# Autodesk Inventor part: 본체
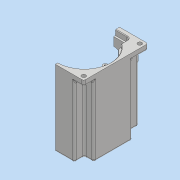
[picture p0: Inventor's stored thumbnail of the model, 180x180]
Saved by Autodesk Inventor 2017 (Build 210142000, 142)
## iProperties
Part Number: 본체
Material: 일반
Document SubType Name: Modeling
Designer: user
Density: 1 g/cm^3
Appearance: 기본값
Author: user
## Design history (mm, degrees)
sketch "스케치1"
  geometry: L1 (-49, 60)-(49, 60); L2 (49, 60)-(49, -50); L3 (49, -50)-(-49, -50); L4 (-49, -50)-(-49, 60); 2 further points
  constraints: 8 end point, 2 parallel, 1 horizontal, 1 midpoint, 1 perpendicular, 1 vertical alignment
  dimensions: "d0" = 98 distance of L2.end L3.end; "d1" = 110 distance of L1.end L2.end; "d2" = 50 distance from line of point (0, 0) L3
extrude "돌출1" new body sketch "스케치1" distance "d3" = 130; taper "d4" = 0 deg
sketch "스케치9"
  geometry: L1 (-49, 60)-(-33, 60); L2 (-33, 60)-(-33, 33); L3 (-33, 33)-(-49, 33); L4 (-49, 33)-(-49, 60); L5 (49, 60)-(33, 60); L6 (33, 60)-(33, 33); L7 (33, 33)-(49, 33); L8 (49, 33)-(49, 60); L9 (-49, -50)-(-33, -50); L10 (-33, -50)-(-33, -33); L11 (-33, -33)-(-49, -33); L12 (-49, -33)-(-49, -50); L13 (49, -50)-(33, -50); L14 (33, -50)-(33, -33); L15 (33, -33)-(49, -33); L16 (49, -33)-(49, -50); 1 further point
  constraints: 32 end point, 8 parallel, 4 horizontal, 4 perpendicular
  dimensions: "d84" = 16 distance of L2.end L3.end; "d85" = 27 distance of L1.end L2.end; "d86" = 16 distance of L7.end L6.end; "d87" = 27 distance of L6.end L5.end; "d88" = 16 distance of L11.end L10.end; "d89" = 17 distance of L10.end L9.end; "d90" = 16 distance of L14.end L15.end; "d91" = 17 distance of L13.end L14.end
extrude "돌출9" cut sketch "스케치9" distance "d92" = 120; taper "d93" = 0 deg
fillet "모깎기12" dims "d94" = 3
sketch "스케치2"
  geometry: L1 (-23, 50)-(23, 50); L2 (23, 50)-(23, 35.143); L3 (-23, 35.143)-(-23, 50); A1 r 42 centre (0, 0) between (-23, 35.143) and (23, 35.143); 2 further points
  constraints: 6 end point, 2 point on circle, 1 centre point, 1 coincident, 1 horizontal, 1 midpoint, 1 parallel, 1 perpendicular, 1 vertical alignment
  dimensions: "d5" = 84 diameter of A1; "d6" = 50 distance from line of point (0, 0) L1; "d7" = 46 distance of L1.start L1.end
extrude "돌출2" cut sketch "스케치2" distance "d8" = 121; taper "d9" = 0 deg
sketch "스케치3"
  geometry: L1 (-23, 35.143)-(-23, 50) reference; L2 (-23, 50)-(23, 50) reference; L3 (23, 50)-(23, 35.143) reference; L4 (-26, 36.729)-(-26, 53); L5 (-26, 53)-(26, 53); L6 (26, 53)-(26, 36.729); A1 r 42 centre (0, 0) between (-23, 35.143) and (23, 35.143) reference; A2 r 45 centre (0, 0) between (-26, 36.729) and (26, 36.729)
  constraints: 6 end point, 2 point on circle, 1 centre point, 3 other
  dimensions: "d10" = 3 radial gap between concentric circles of A2 A1
extrude "돌출3" cut sketch "스케치3" distance "d11" = 9; taper "d12" = 0 deg
fillet "모깎기1" dims "d13" = 6
fillet "모깎기2" dims "d14" = 3
fillet "모깎기3" dims "d15" = 3
fillet "모깎기4" dims "d16" = 6
sketch "스케치4"
  geometry: L1 (36, 4)-(41.809, 4); L2 (36, -4)-(41.809, -4); A1 r 45 centre (0, 0) between (-27.188, 35.859) and (27.188, 35.859) reference; A2 r 42 centre (0, 0) between (-25.375, 33.468) and (25.375, 33.468) reference; A3 r 4 centre (36, 0) between (36, 4) and (36, -4)
  constraints: 4 end point, 4 point on circle, 2 horizontal, 2 tangent, 1 centre point, 1 horizontal alignment
  dimensions: "d17" = 8 diameter of A3; "d18" = 36 distance of A3.centre A1.centre
extrude "돌출4" join sketch "스케치4" stored distance "d19" = 9; taper "d20" = 0 deg
hole "구멍1" diameter "d23" = 3.242; stored, may be unused: countersink angle "d27" = 90 deg, drill point angle "d29" = 118 deg; dims "d21" = 10, "d22" = 10, "d24" = 7, "d25" = 4, "d26" = 2, "d28" = 9
sketch "스케치5"
  geometry: A1 r 42 centre (0, 0) between (-41.809, -4) and (41.809, -4) reference; A2 r 42 centre (0, 0) between (41.809, 4) and (25.375, 33.468) reference; A3 r 21 centre (0, 11) between (8.978, -7.984) and (-8.978, -7.984); A4 r 15 centre (0, -20) between (-8.978, -7.984) and (8.978, -7.984)
  constraints: 4 point on circle, 2 centre point, 2 vertical alignment
  dimensions: "d30" = 42 diameter of A3; "d31" = 30 diameter of A4; "d32" = 11 distance of A1.centre A3.centre; "d33" = 20 distance of A4.centre A1.centre
extrude "돌출5" join sketch "스케치5" distance "d34" = 7; taper "d35" = 0 deg
fillet "모깎기5" dims "d36" = 3
hole "구멍2" diameter "d39" = 19; stored, may be unused: countersink angle "d43" = 90 deg, drill point angle "d45" = 0 deg; dims "d37" = 10, "d38" = 10, "d40" = 7, "d41" = 22, "d42" = 7, "d44" = 10
fillet "모깎기6" dims "d46" = 0.3
chamfer "모따기1" distance "d47" = 1; stored, may be unused: second distance "d48" = 2, angle "d49" = 45 deg
fillet "모깎기7" dims "d50" = 3
hole "구멍3" diameter "d53" = 28; stored, may be unused: countersink angle "d57" = 90 deg, drill point angle "d59" = 0 deg; dims "d51" = 10, "d52" = 10, "d54" = 7, "d55" = 35, "d56" = 10, "d58" = 10
sketch "스케치6"
  geometry: L1 (27, -16)-(-27, -16); L2 (-27, -16)-(-27, 38); L3 (-27, 38)-(27, 38); L4 (27, 38)-(27, -16); L5 (27, -16)-(-27, 38); L6 (-27, -16)-(27, 38); C1 r 14 at (0, 11) reference; 1 further point
  constraints: 12 end point, 2 midpoint, 2 parallel, 1 horizontal, 1 perpendicular
  dimensions: "d60" = 54 distance of L2.end L3.end; "d61" = 54 distance of L1.end L2.end
extrude "돌출6" join sketch "스케치6" distance "d62" = 7; taper "d63" = 0 deg
sketch "스케치7"
  geometry: C1 r 14 at (0, 11) reference; C2 r 16 at (0, 11); 1 further point
  constraints: 1 centre point, 1 coincident
  dimensions: "d64" = 32 diameter of C2
extrude "돌출7" cut sketch "스케치7" distance "d65" = 8.3; taper "d66" = 0 deg
chamfer "모따기2" distance "d67" = 0.8; stored, may be unused: second distance "d68" = 2, angle "d69" = 30 deg
fillet "모깎기8" dims "d70" = 0.3
fillet "모깎기9" dims "d71" = 0.3
fillet "모깎기10" dims "d72" = 3
fillet "모깎기11" dims "d73" = 3
fillet "모깎기13" dims "d95" = 3
fillet "모깎기14" dims "d96" = 3
fillet "모깎기15" dims "d97" = 3
sketch "스케치10"
  geometry: L1 (-46, 60)-(46, 60) reference; A1 r 45 centre (0, 0) between (-27.188, 35.859) and (27.188, 35.859) reference; 4 further points
  constraints: 2 horizontal alignment, 2 vertical alignment
  dimensions: "d98" = 84 distance of point (42, 53) point (-42, 53); "d99" = 42 horizontal distance of A1.centre point (42, 53) (= 0.5 x d98); "d100" = 96 distance of point (42, -43) point (42, 53); "d101" = 7 distance from line of L1 point (42, 53)
hole "구멍4" sketch "스케치10" at (-42, 53), (-42, -43), (42, -43), (42, 53) diameter "d102" = 7; stored, may be unused: countersink angle "d106" = 90 deg, drill point angle "d108" = 0 deg; dims "d103" = 7, "d104" = 35, "d105" = 10, "d107" = 10
sketch "스케치11"
  geometry: L1 (0, 0)-(92, 0) reference; C1 r 15 at (46, 89); C2 r 22.5 at (46, 40); 2 further points
  constraints: 2 centre point, 2 vertical alignment, 1 midpoint
  dimensions: "d109" = 30 diameter of C1; "d110" = 45 diameter of C2; "d111" = 40 distance from line of C2.centre L1; "d112" = 49 distance of C1.centre C2.centre
extrude "돌출10" join sketch "스케치11" distance "d113" = 5; taper "d114" = 0 deg
extrude "돌출11" join sketch "스케치11" distance "d115" = 10; taper "d116" = 0 deg
hole "구멍5" diameter "d119" = 20; stored, may be unused: countersink angle "d123" = 90 deg, drill point angle "d125" = 0 deg; dims "d117" = 10, "d118" = 10, "d120" = 7, "d121" = 30, "d122" = 5, "d124" = 10
hole "구멍6" diameter "d128" = 33.376; stored, may be unused: countersink angle "d132" = 90 deg, drill point angle "d134" = 0 deg; dims "d126" = 10, "d127" = 10, "d129" = 70, "d130" = 30, "d131" = 5, "d133" = 77.3
fillet "모깎기16" dims "d135" = 3
sketch "스케치12"
  geometry: L1 (-13, 80)-(-127, 80) reference; L2 (-130, 104)-(-130, 83) reference; 2 further points
  constraints: 1 other
  dimensions: "d136" = 33 distance from line of point (-65, 47) L1; "d137" = 65 distance from line of point (-65, 47) L2
feature "엠보싱1" sketch "스케치12" dims "d138" = 0.5, "d139" = 0
fillet "모깎기17" dims "d140" = 3
fillet "모깎기18" dims "d141" = 3
chamfer "모따기3" distance "d142" = 1; stored, may be unused: second distance "d143" = 2, angle "d144" = 30 deg
chamfer "모따기4" distance "d145" = 1; stored, may be unused: second distance "d146" = 2, angle "d147" = 45 deg
chamfer "모따기5" distance "d148" = 1; stored, may be unused: second distance "d149" = 2, angle "d150" = 45 deg
node "솔리드1"
mirror "미러1"
